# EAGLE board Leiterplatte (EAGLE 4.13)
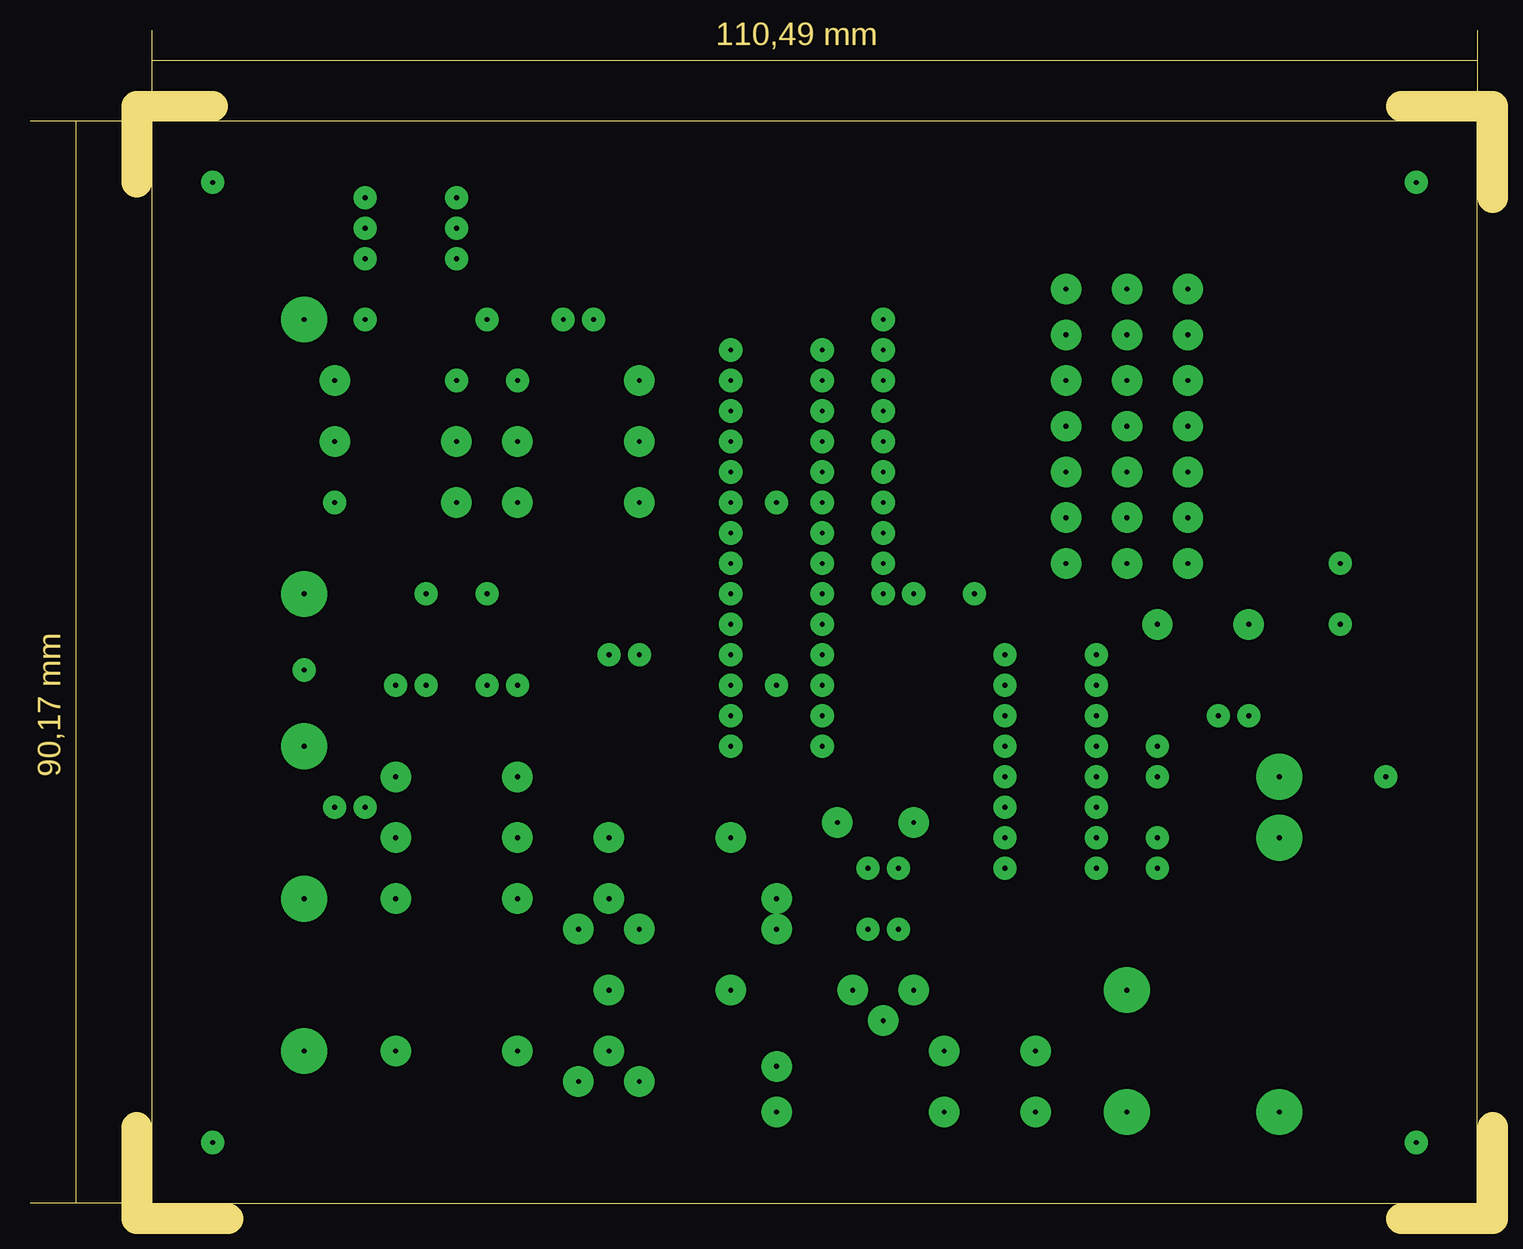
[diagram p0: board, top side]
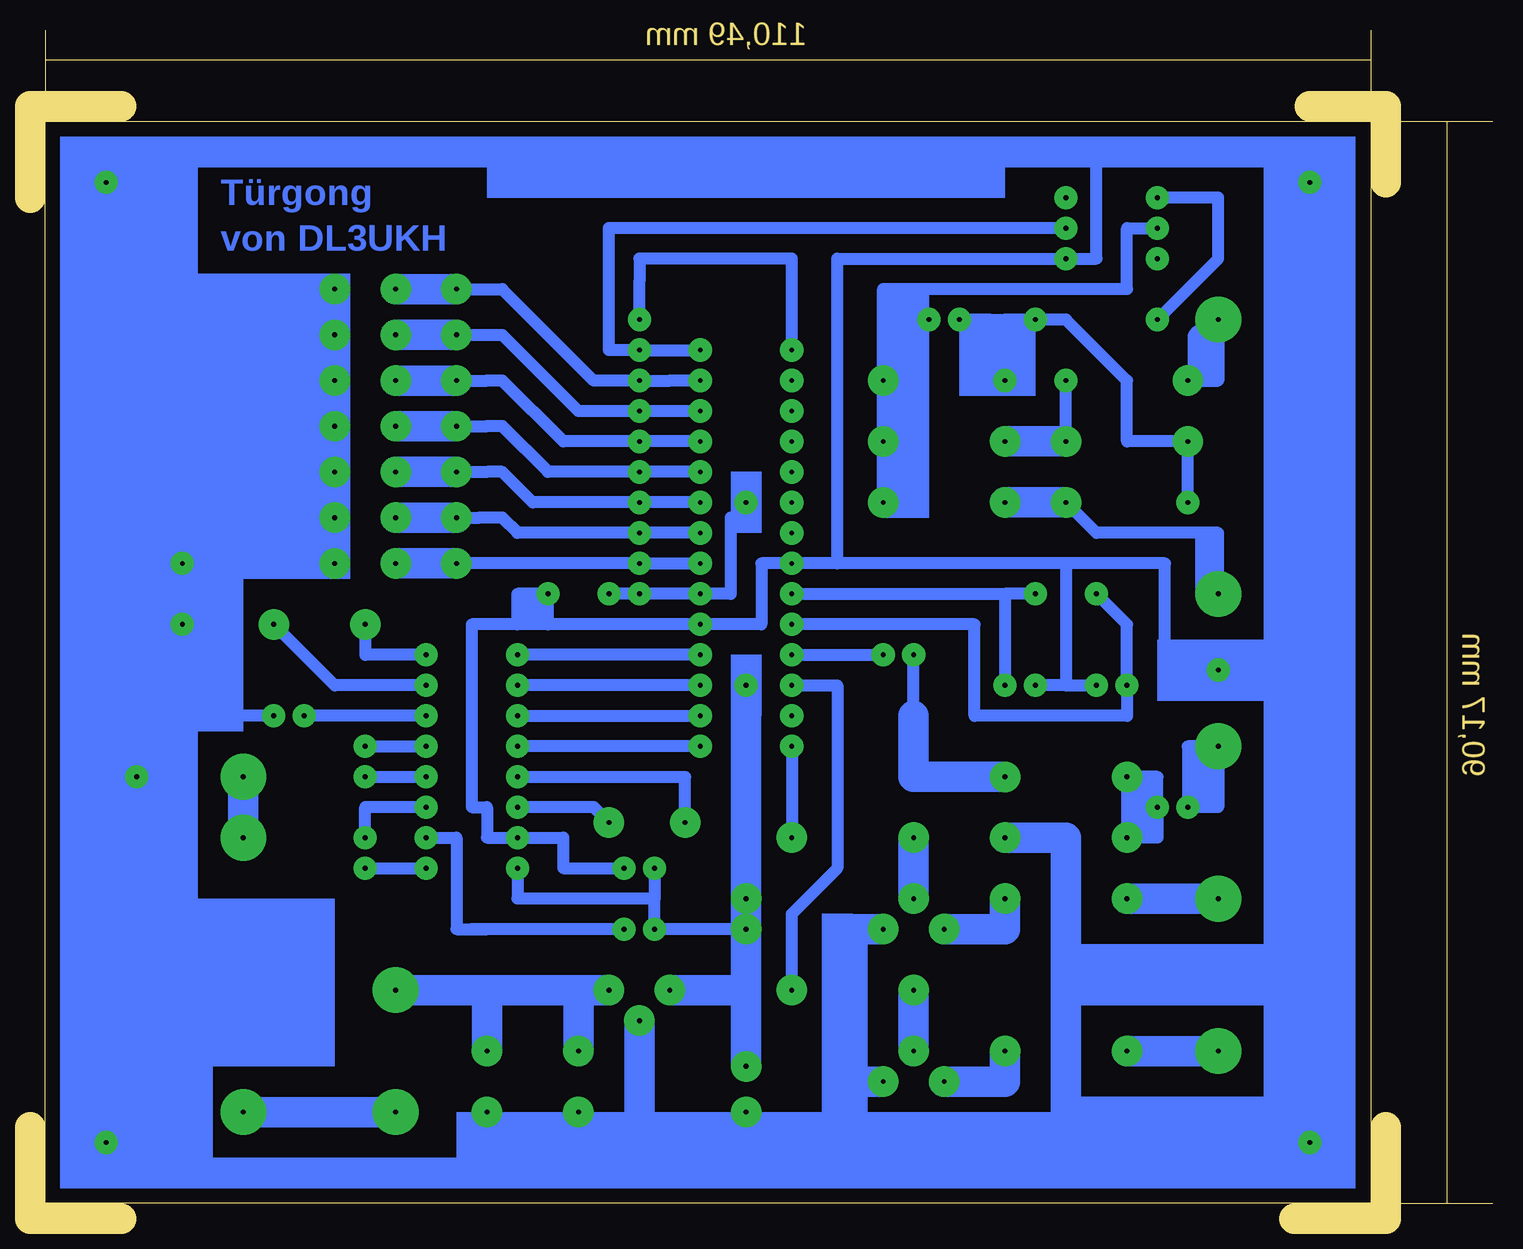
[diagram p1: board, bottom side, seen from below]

Size 121.92 x 99.06 mm. Coordinates in mm from the lower left corner, seen from the top.
Outline: 10.16,1.27 120.65,1.27 120.65,91.44 10.16,91.44
Outline: 10.16,91.44 10.16,1.27
Outline: 15.24,92.71 10.16,92.71
Outline: 10.16,92.71 8.89,92.71 8.89,86.36
Outline: 114.3,92.71 120.65,92.71
Outline: 120.65,92.71 121.92,92.71 121.92,85.09
Outline: 8.89,7.62 8.89,0 16.51,0
Outline: 114.3,0 121.92,0 121.92,7.62
Outline: 10.16,91.44 3.81,91.44
Outline: 3.81,91.44 0,91.44
Outline: 10.16,1.27 3.81,1.27
Outline: 3.81,1.27 0,1.27
Outline: 3.81,91.44 3.81,1.27
Outline: 10.16,99.06 10.16,96.52
Outline: 10.16,96.52 10.16,92.71
Outline: 120.65,99.06 120.65,96.52
Outline: 120.65,96.52 120.65,92.71
Outline: 10.16,96.52 120.65,96.52
Copper layers (1*16): Top 0.035mm / dielectric 1.5mm / Bottom 0.035mm
Design rules "default": minimum track width 10mil, minimum drill 24mil, track to track 8mil, track to pad 8mil, pad to pad 8mil, via to via 8mil, smd to smd 8mil, copper to edge 40mil, drill to drill 8mil, minimum pad ring 10mil, minimum via ring 8mil, stop-mask expansion 4mil, vias tented up to drill 0mil, thermal gap 10mil

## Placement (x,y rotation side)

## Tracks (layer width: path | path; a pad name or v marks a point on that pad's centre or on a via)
S$1  (via drill 0.4 pad 1.93, 0.4 pad 2.54)
  Bottom 1.016: v58.42,39.37 v58.42,31.75
S$2  (via drill 0.4 pad 1.93)
  other vias: 58.42,41.91
S$3  (via drill 0.4 pad 1.93, 0.4 pad 2.54)
  Bottom 1.016: v58.42,44.45 54.61,44.45 54.61,29.21 58.42,25.4 v58.42,19.05
S$4  (via drill 0.4 pad 2.54, 0.4 pad 3.81)
  Bottom 1.016: v22.86,74.93 22.86,69.85 v25.4,69.85
  Bottom 1.27: v22.86,74.93 24.77,73.66
S$5  (via drill 0.4 pad 1.93)
  Bottom 1.016: v58.42,46.99 v50.8,46.99
S$6  (via drill 0.4 pad 1.93, 0.4 pad 2.54)
  Bottom 1.016: v66.04,59.69 v71.12,59.69 80.01,59.69 82.55,62.23 83.82,62.23 86.99,62.23
  Bottom 2.54: v86.36,62.23 86.99,62.23 v91.44,62.23
S$7  (via drill 0.4 pad 1.93)
  Bottom 1.016: v88.9,31.75 86.36,31.75 86.36,24.13 83.82,24.13 | 83.82,24.13 85.09,24.13 | v72.39,24.13 83.82,24.13
S$8  (via drill 0.4 pad 1.93)
  other vias: 58.42,57.15
S$9  (via drill 0.4 pad 1.93)
  other vias: 58.42,59.69
S$10  (via drill 0.4 pad 1.93)
  other vias: 58.42,62.23
S$11  (via drill 0.4 pad 1.93)
  other vias: 58.42,64.77
S$12  (via drill 0.4 pad 1.93)
  other vias: 58.42,67.31
S$13  (via drill 0.4 pad 1.93)
  other vias: 58.42,69.85
S$14  (via drill 0.4 pad 1.93)
  Bottom 1.016: v58.42,72.39 58.42,80.01 71.12,80.01 71.12,78.1 v71.12,74.93
S$15  (via drill 0.4 pad 1.93)
  Bottom 1.016: v66.04,72.39 v71.12,72.39 73.66,72.39 73.66,82.55 v35.56,82.55
S$16  (via drill 0.4 pad 1.93)
  Bottom 1.016: v66.04,69.85 68.58,69.85 v71.12,69.85
S$17  (via drill 0.4 pad 2.54)
  Bottom 1.016: 71.75,64.77 77.47,64.77 82.55,69.85 83.82,69.85 v86.36,69.85
  Bottom 2.54: v86.36,69.85 v91.44,69.85
S$18  (via drill 0.4 pad 1.93)
  Bottom 1.016: v66.04,64.77 v71.12,64.77
S$19  (via drill 0.4 pad 2.54)
  Bottom 2.54: v48.26,26.67 v48.26,31.75
S$20  (via drill 0.4 pad 1.93, 0.4 pad 2.54)
  Bottom 1.016: 48.26,41.91 v48.26,46.99
  Bottom 2.54: v40.64,36.83 48.26,36.83 48.26,41.91
S$21  (via drill 0.4 pad 2.54)
  Bottom 2.54: v40.64,13.97 40.64,11.43 v45.72,11.43
S$22  (via drill 0.4 pad 1.93, 0.4 pad 2.54)
  Bottom 1.016: v66.04,54.61 v71.12,54.61 v86.36,54.61
  Bottom 2.54: v91.44,54.61 v86.36,54.61
S$23  (via drill 0.4 pad 1.93)
  Bottom 1.016: v73.66,52.07 v71.12,52.07 v66.04,52.07 63.5,52.07 63.5,58.42 62.23,58.42 v62.23,59.69
S$24  (via drill 0.4 pad 1.93, 0.4 pad 2.54)
  Bottom 1.016: v66.04,62.23 v71.12,62.23 78.74,62.23 82.55,66.04 83.82,66.04 v86.36,66.04
  Bottom 2.54: v86.36,66.04 v91.44,66.04
S$25  (via drill 0.4 pad 1.93)
  Bottom 1.016: v66.04,46.99 v81.28,46.99
S$26  (via drill 0.4 pad 1.93)
  Bottom 1.016: v66.04,44.45 v81.28,44.45
S$27  (via drill 0.4 pad 1.93)
  Bottom 1.016: v81.28,41.91 v66.04,41.91
S$28  (via drill 0.4 pad 1.93)
  Bottom 1.016: v66.04,39.37 v81.28,39.37
S$29  (via drill 0.4 pad 1.93, 0.4 pad 2.54)
  Bottom 1.016: v66.04,57.15 v71.12,57.15 81.28,57.15 82.55,58.42 84.45,58.42 v86.36,58.42
  Bottom 2.54: v86.36,58.42 v91.44,58.42
S$30  (via drill 0.4 pad 2.54)
  Bottom 2.54: v48.26,13.97 v48.26,19.05
S$31  (via drill 0.4 pad 2.54, 0.4 pad 3.81)
  Bottom 2.54: v30.48,26.67 v22.86,26.67
S$32  (via drill 0.4 pad 1.93)
  Bottom 1.016: v38.1,52.07 40.64,52.07 | v58.42,52.07 40.64,52.07 | 40.64,52.07 v40.64,44.45
S$33  (via drill 0.4 pad 3.81)
  Bottom 1.016: v104.14,8.89 v91.44,8.89
  Bottom 2.54: v91.44,8.89 v104.14,8.89
S$34  (via drill 0.4 pad 1.93, 0.4 pad 2.54)
  Bottom 1.016: v27.94,34.29 27.94,36.83 v30.48,36.83 v30.48,31.75 27.94,31.75 v27.94,34.29
S$35  (via drill 0.4 pad 2.54)
  Bottom 2.54: v96.52,54.61 v96.52,69.85
S$36  (via drill 0.4 pad 1.93)
  Bottom 1.016: 27.3,46.36 27.3,54.61 35.56,54.61 | v72.39,29.21 77.47,29.21 77.47,31.75 v81.28,31.75 83.82,31.75 83.82,34.29 85.09,34.29 85.09,49.53 81.28,49.53 | 78.74,49.53 v66.04,49.53 60.96,49.53 60.96,54.61 v58.42,54.61 54.61,54.61 | 78.74,49.53 81.28,49.53 | 35.56,44.45 v38.1,44.45 | 35.56,54.61 35.56,44.45 | 35.56,44.45 v33.02,44.45 | 54.61,54.61 54.61,80.01 v35.56,80.01 33.02,80.01 33.02,88.9 | 81.28,49.53 81.28,52.07 v78.74,52.07 78.74,49.53 | 35.56,54.61 54.61,54.61
S$37  (via drill 0.4 pad 1.93)
  other vias: 115.57,6.35
S$38  (via drill 0.4 pad 1.93, 0.4 pad 3.81)
  Bottom 1.016: v22.86,39.37 25.4,39.37 v25.4,34.29 22.86,34.29 v22.86,39.37
S$39  (via drill 0.4 pad 1.93, 0.4 pad 2.54)
  Bottom 1.016: v81.28,36.83 67.31,36.83 v67.31,33.02
S$40  (via drill 0.4 pad 1.93)
  other vias: 115.57,86.36
S$41  (via drill 0.4 pad 2.54)
  other vias: 96.52,58.42
S$42  (via drill 0.4 pad 1.93)
  Bottom 1.016: v93.98,29.21 v88.9,29.21
S$43  (via drill 0.4 pad 1.93, 0.4 pad 2.54)
  Bottom 1.016: v96.52,62.23 106.68,64.77 106.68,41.91 v101.6,41.91
S$44  (via drill 0.4 pad 1.93)
  Bottom 1.016: v88.9,34.29 93.98,34.29 v93.98,31.75
S$45  (via drill 0.4 pad 1.93)
  Bottom 1.016: v93.98,36.83 v88.9,36.83
S$46  (via drill 0.4 pad 1.93)
  Bottom 1.016: v93.98,39.37 v88.9,39.37
S$47  (via drill 0.4 pad 1.93)
  Bottom 1.016: v88.9,41.91 v99.06,41.91
S$48  (via drill 0.4 pad 1.93, 0.4 pad 2.54)
  Bottom 1.016: v88.9,44.45 96.52,44.45 v101.6,49.53
S$49  (via drill 0.4 pad 1.93, 0.4 pad 2.54)
  Bottom 1.016: v93.98,49.53 93.98,46.99 v88.9,46.99
S$50  (via drill 0.4 pad 2.54)
  other vias: 96.52,66.04
S$51  (via drill 0.4 pad 2.54)
  Bottom 1.016: 71.75,69.85 74.93,69.85 82.55,77.47 v86.36,77.47
  Bottom 2.54: v86.36,77.47 88.27,77.47 v91.44,77.47
S$52  (via drill 0.4 pad 3.81)
  Bottom 2.54: v104.14,31.75 v104.14,36.83
S$53  (via drill 0.4 pad 1.93)
  Bottom 1.016: v33.02,52.07 30.48,49.53 v30.48,44.45 30.48,41.91 43.18,41.91 43.18,49.53 v58.42,49.53
S$54  (via drill 0.4 pad 1.93)
  other vias: 35.56,85.09
S$55  (via drill 0.4 pad 1.93, 0.4 pad 2.54)
  Bottom 1.016: v27.94,82.55 30.48,82.55 30.48,77.47 50.8,77.47 50.8,73.66 | v46.99,74.93 50.8,74.93 50.8,73.66 | 50.8,73.66 v50.8,69.85 v50.8,64.77 v50.8,59.69
S$56  (via drill 0.4 pad 2.54, 0.4 pad 3.81)
  Bottom 2.54: v30.48,13.97 v22.86,13.97
S$57  (via drill 0.4 pad 1.93)
  other vias: 113.03,36.83
S$58  (via drill 0.4 pad 2.54)
  Bottom 2.54: v40.64,26.67 40.64,24.13 v45.72,24.13
S$59  (via drill 0.4 pad 1.93)
  other vias: 15.24,6.35
S$60  (via drill 0.4 pad 1.93, 0.4 pad 2.54)
  Bottom 1.016: v62.23,26.67 v62.23,44.45 | v62.23,24.13 v69.85,24.13 69.85,26.67 | v69.85,29.21 69.85,26.67 | 69.85,26.67 81.28,26.67 v81.28,29.21
  Bottom 2.54: v62.23,44.45 v62.23,26.67 v62.23,24.13 62.23,19.05 | 62.23,19.05 v62.23,12.7 | 62.23,19.05 v68.58,19.05
S$61  (via drill 0.4 pad 1.93)
  other vias: 27.94,80.01
S$62  (via drill 0.4 pad 1.93, 0.4 pad 2.54)
  Bottom 1.016: v73.66,33.02 74.93,34.29 v81.28,34.29
S$63  (via drill 0.4 pad 1.93)
  other vias: 15.24,86.36
S$64  (via drill 0.4 pad 2.54, 0.4 pad 3.81)
  Bottom 1.016: 76.2,19.05 83.82,19.05
  Bottom 2.54: v76.2,13.97 76.2,19.05 v73.66,19.05 83.82,19.05 | v91.44,19.05 83.82,19.05 | 83.82,19.05 v83.82,13.97
S$65  (via drill 0.4 pad 2.54)
  Bottom 1.016: 35.56,6.35 53.34,6.35 62.23,6.35 71.12,6.35 76.2,6.35 | v83.82,8.89 83.82,6.35 76.2,6.35 | v76.2,8.89 76.2,6.35
  Bottom 2.54: v71.12,16.51 71.12,6.35 | v76.2,8.89 76.2,5.08 | v83.82,8.89 83.82,5.08 | v50.8,24.13 53.34,24.13 53.34,11.43 | 53.34,6.35 53.34,11.43 | 53.34,11.43 v50.8,11.43 | v40.64,31.75 35.56,31.75 35.56,6.35 | v62.23,8.89 62.23,6.35
S$66  (via drill 0.4 pad 1.93)
  other vias: 109.22,49.53
S$67  (via drill 0.4 pad 1.93)
  other vias: 109.22,54.61
S$68  (via drill 0.4 pad 1.93)
  other vias: 22.86,45.72
S$73  (via drill 0.4 pad 1.93)
  Bottom 1.016: v27.94,85.09 22.86,85.09 22.86,80.01 v27.94,74.93
S$75  (via drill 0.4 pad 1.93, 0.4 pad 2.54)
  Bottom 1.016: v35.56,64.77 v35.56,69.85
  Bottom 2.54: v35.56,64.77 38.1,64.77 v40.64,64.77
S$76  (via drill 0.4 pad 2.54, 0.4 pad 3.81)
  Bottom 1.016: 22.86,54.61 v22.86,52.07 22.86,57.15 33.02,57.15 v35.56,59.69 v40.64,59.69
  Bottom 2.54: v35.56,59.69 v40.64,59.69
S$78  (via drill 0.4 pad 1.93, 0.4 pad 2.54)
  Bottom 1.016: v25.4,59.69 v25.4,64.77 30.48,64.77 30.48,69.85 35.56,74.93 v38.1,74.93 40.64,74.93 | v44.45,74.93 41.91,74.93 40.64,74.93 | v40.64,69.85 40.64,74.93
S$81  (via drill 0.4 pad 1.93, 0.4 pad 2.54)
  Bottom 1.016: v66.04,67.31 v71.12,67.31 76.2,67.31 82.55,73.66 v86.36,73.66
  Bottom 2.54: v86.36,73.66 88.27,73.66 v91.44,73.66
S$83  (via drill 0.4 pad 2.54)
  other vias: 96.52,73.66
S$84  (via drill 0.4 pad 2.54)
  other vias: 96.52,77.47
(copper drawn outside any net)
  shapes: Bottom area x34

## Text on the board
Bottom: Türgong | von DL3UKH
Dimension: 110,49 mm | 90,17 mm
